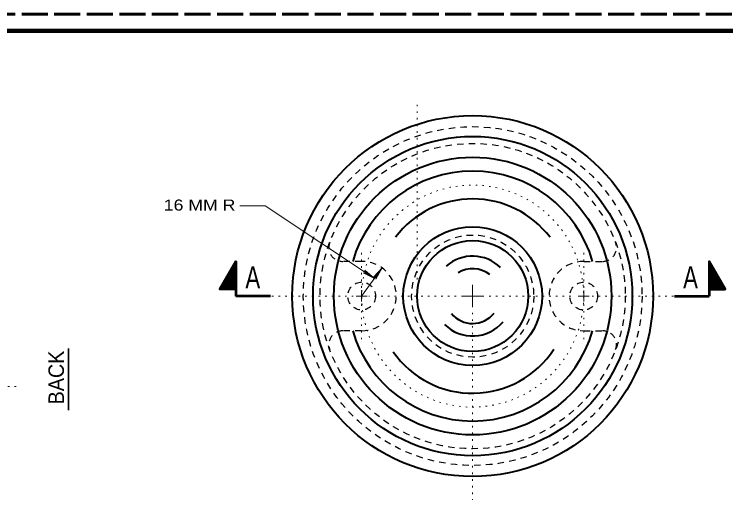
# Model space of a CAD drawing. Extents: x 312583 to 312853, y 144419 to 144586.
# Drawn here: x 312716.69 to 312765.82, y 144552.16 to 144586.22 of the extents above; entities that cross this region are included whole.
import ezdxf
from ezdxf.enums import TextEntityAlignment as Align

# ---------------------------------------------------------------- set-up
doc = ezdxf.new("R2010")
doc.units = 0
doc.header["$LTSCALE"] = 0.3
for name, pattern in [('DOTTED', [1.5, 0.3, -1.2]), ('LONG_DASHED', [7.5, 6, -1.5]), ('SHORT_DASHED', [2.7, 1.5, -1.2])]:
    doc.linetypes.add(name, pattern=pattern)
for name, color, linetype, lineweight in [('1', 7, 'Continuous', 40), ('2', 7, 'Continuous', 13), ('63', 7, 'LONG_DASHED', 60)]:
    doc.layers.add(name, color=color, linetype=linetype, lineweight=lineweight)

msp = doc.modelspace()

# ---------------------------------------------------------------- linework, layer by layer
at = {"layer": '1', "lineweight": 35}
for p, q in [((312731.9925, 144569.0873), (312731.9542, 144569.1103)), ((312731.9925, 144569.1179), (312731.9695, 144569.1256)), ((312731.9925, 144569.1486), (312731.9772, 144569.1486)), ((312764.6679, 144569.1486), (312764.6832, 144569.1486)), ((312764.6679, 144569.1179), (312764.6909, 144569.1256)), ((312764.6679, 144569.0873), (312764.7062, 144569.1103)), ((312731.9925, 144568.4509), (312731.6859, 144568.6273)), ((312731.9925, 144568.4816), (312731.6935, 144568.6503)), ((312731.9925, 144568.5123), (312731.7089, 144568.6733)), ((312731.9925, 144568.5353), (312731.7165, 144568.6886)), ((312731.9925, 144568.5659), (312731.7319, 144568.7193)), ((312731.9925, 144568.5889), (312731.7395, 144568.7346)), ((312731.9925, 144568.6196), (312731.7549, 144568.7576)), ((312731.9925, 144568.6503), (312731.7625, 144568.7806)), ((312731.9925, 144568.6733), (312731.7779, 144568.7959)), ((312731.9925, 144568.7039), (312731.7855, 144568.8189)), ((312731.9925, 144568.7269), (312731.8009, 144568.8419)), ((312731.9925, 144568.7576), (312731.8162, 144568.8573)), ((312731.9925, 144568.7883), (312731.8239, 144568.8803)), ((312731.9925, 144568.8189), (312731.8392, 144568.9033)), ((312731.9925, 144568.8419), (312731.8545, 144568.9186)), ((312731.9925, 144568.8726), (312731.8622, 144568.9416)), ((312731.9925, 144568.8956), (312731.8775, 144568.9646)), ((312731.9925, 144568.9186), (312731.8852, 144568.9876)), ((312731.9925, 144568.9493), (312731.9005, 144569.0029)), ((312731.9925, 144568.9799), (312731.9082, 144569.0259)), ((312731.9925, 144569.0106), (312731.9235, 144569.0489)), ((312731.9925, 144569.0336), (312731.9312, 144569.0643)), ((312731.9925, 144569.0643), (312731.9465, 144569.0873)), ((312764.6679, 144569.0643), (312764.7139, 144569.0873)), ((312764.6679, 144569.0336), (312764.7292, 144569.0643)), ((312764.6679, 144569.0106), (312764.7369, 144569.0489)), ((312764.6679, 144568.9799), (312764.7522, 144569.0259)), ((312764.6679, 144568.9493), (312764.7599, 144569.0029)), ((312764.6679, 144568.9186), (312764.7752, 144568.9876)), ((312764.6679, 144568.8956), (312764.7829, 144568.9646)), ((312764.6679, 144568.8726), (312764.7982, 144568.9416)), ((312764.6679, 144568.8419), (312764.8059, 144568.9186)), ((312764.6679, 144568.8189), (312764.8212, 144568.9033)), ((312764.6679, 144568.7883), (312764.8365, 144568.8803)), ((312764.6679, 144568.7576), (312764.8442, 144568.8573)), ((312764.6679, 144568.7269), (312764.8595, 144568.8419)), ((312764.6679, 144568.7039), (312764.8749, 144568.8189)), ((312764.6679, 144568.6733), (312764.8825, 144568.7959)), ((312764.6679, 144568.6503), (312764.8979, 144568.7806)), ((312764.6679, 144568.6196), (312764.9055, 144568.7576)), ((312764.6679, 144568.5889), (312764.9209, 144568.7346)), ((312764.6679, 144568.5659), (312764.9285, 144568.7193)), ((312764.6679, 144568.5353), (312764.9439, 144568.6886)), ((312764.6679, 144568.5123), (312764.9515, 144568.6733)), ((312764.6679, 144568.4816), (312764.9669, 144568.6503)), ((312764.6679, 144568.4509), (312764.9745, 144568.6273)), ((312731.9925, 144567.7916), (312731.3945, 144568.1289)), ((312731.9925, 144567.8223), (312731.4099, 144568.1519)), ((312731.9925, 144567.8453), (312731.4175, 144568.1749)), ((312731.9925, 144567.8759), (312731.4329, 144568.1903)), ((312731.9849, 144567.8989), (312731.4405, 144568.2209)), ((312731.9925, 144567.9296), (312731.4559, 144568.2363)), ((312731.9925, 144567.9526), (312731.4712, 144568.2593)), ((312731.9925, 144567.9833), (312731.4789, 144568.2823)), ((312731.9925, 144568.0139), (312731.4942, 144568.2976)), ((312731.9925, 144568.0369), (312731.5019, 144568.3206)), ((312731.9925, 144568.0676), (312731.5172, 144568.3436)), ((312731.9925, 144568.0983), (312731.5249, 144568.3589)), ((312731.9925, 144568.1213), (312731.5402, 144568.3819)), ((312731.9925, 144568.1519), (312731.5479, 144568.4049)), ((312731.9925, 144568.1826), (312731.5632, 144568.4203)), ((312731.9925, 144568.2056), (312731.5709, 144568.4433)), ((312731.9925, 144568.2286), (312731.5862, 144568.4663)), ((312731.9925, 144568.2593), (312731.5939, 144568.4893)), ((312731.9925, 144568.2899), (312731.6092, 144568.5046)), ((312731.9925, 144568.3206), (312731.6245, 144568.5276)), ((312731.9925, 144568.3436), (312731.6322, 144568.5506)), ((312731.9925, 144568.3743), (312731.6475, 144568.5659)), ((312731.9925, 144568.3973), (312731.6629, 144568.5889)), ((312731.9925, 144568.4279), (312731.6705, 144568.6119)), ((312764.6679, 144568.4279), (312764.9899, 144568.6119)), ((312764.6679, 144568.3973), (312764.9975, 144568.5889)), ((312764.6679, 144568.3743), (312765.0129, 144568.5659)), ((312764.6679, 144568.3436), (312765.0282, 144568.5506)), ((312764.6679, 144568.3206), (312765.0359, 144568.5276)), ((312764.6679, 144568.2899), (312765.0512, 144568.5046)), ((312764.6679, 144568.2593), (312765.0665, 144568.4893)), ((312764.6679, 144568.2286), (312765.0742, 144568.4663)), ((312764.6679, 144568.2056), (312765.0895, 144568.4433)), ((312764.6679, 144568.1826), (312765.0972, 144568.4203)), ((312764.6679, 144568.1519), (312765.1125, 144568.4049)), ((312764.6679, 144568.1213), (312765.1202, 144568.3819)), ((312764.6679, 144568.0983), (312765.1355, 144568.3589)), ((312764.6679, 144568.0676), (312765.1432, 144568.3436)), ((312764.6679, 144568.0369), (312765.1585, 144568.3206)), ((312764.6679, 144568.0139), (312765.1662, 144568.2976)), ((312764.6679, 144567.9833), (312765.1815, 144568.2823)), ((312764.6679, 144567.9526), (312765.1892, 144568.2593)), ((312764.6679, 144567.9296), (312765.2045, 144568.2363)), ((312764.6679, 144567.8759), (312765.2275, 144568.1903)), ((312764.6679, 144567.8453), (312765.2429, 144568.1749)), ((312764.6679, 144567.8223), (312765.2505, 144568.1519)), ((312764.6679, 144567.7916), (312765.2659, 144568.1289)), ((312764.6755, 144567.8989), (312765.2199, 144568.2209)), ((312731.8239, 144567.2473), (312731.1262, 144567.6536)), ((312731.8775, 144567.2473), (312731.1339, 144567.6766)), ((312731.9159, 144567.2473), (312731.1492, 144567.6919)), ((312731.9695, 144567.2473), (312731.1569, 144567.7226)), ((312731.9925, 144567.2626), (312731.1722, 144567.7379)), ((312731.9925, 144567.2933), (312731.1799, 144567.7609)), ((312731.9925, 144567.3239), (312731.1952, 144567.7839)), ((312731.9925, 144567.3469), (312731.2029, 144567.7993)), ((312731.9925, 144567.3776), (312731.2182, 144567.8223)), ((312731.9849, 144567.4006), (312731.2259, 144567.8453)), ((312731.9849, 144567.4313), (312731.2412, 144567.8606)), ((312731.9925, 144567.4543), (312731.2489, 144567.8836)), ((312731.9925, 144567.4849), (312731.2642, 144567.9066)), ((312731.9925, 144567.5156), (312731.2795, 144567.9219)), ((312731.9925, 144567.5386), (312731.2872, 144567.9449)), ((312731.9925, 144567.5693), (312731.3025, 144567.9679)), ((312731.9925, 144567.5999), (312731.3179, 144567.9909)), ((312731.9925, 144567.6229), (312731.3255, 144568.0063)), ((312731.9849, 144567.6536), (312731.3409, 144568.0293)), ((312731.9925, 144567.6843), (312731.3485, 144568.0523)), ((312731.9925, 144567.7073), (312731.3639, 144568.0676)), ((312731.9925, 144567.7303), (312731.3715, 144568.0906)), ((312731.9925, 144567.7609), (312731.3869, 144568.1136)), ((312764.6679, 144567.7609), (312765.2735, 144568.1136)), ((312764.6679, 144567.7303), (312765.2889, 144568.0906)), ((312764.6679, 144567.7073), (312765.2965, 144568.0676)), ((312764.6679, 144567.6843), (312765.3119, 144568.0523)), ((312764.6679, 144567.6229), (312765.3349, 144568.0063)), ((312764.6679, 144567.5999), (312765.3425, 144567.9909)), ((312764.6679, 144567.5693), (312765.3579, 144567.9679)), ((312764.6679, 144567.5386), (312765.3732, 144567.9449)), ((312764.6679, 144567.5156), (312765.3809, 144567.9219)), ((312764.6679, 144567.4849), (312765.3962, 144567.9066)), ((312764.6679, 144567.4543), (312765.4115, 144567.8836)), ((312764.6679, 144567.3776), (312765.4422, 144567.8223)), ((312764.6679, 144567.3469), (312765.4575, 144567.7993)), ((312764.6679, 144567.3239), (312765.4652, 144567.7839)), ((312764.6679, 144567.2933), (312765.4805, 144567.7609)), ((312764.6679, 144567.2626), (312765.4882, 144567.7379)), ((312764.6755, 144567.6536), (312765.3195, 144568.0293)), ((312764.6755, 144567.4313), (312765.4192, 144567.8606)), ((312764.6755, 144567.4006), (312765.4345, 144567.8453)), ((312764.6909, 144567.2473), (312765.5035, 144567.7226)), ((312764.7445, 144567.2473), (312765.5112, 144567.6919)), ((312764.7829, 144567.2473), (312765.5265, 144567.6766)), ((312764.8365, 144567.2473), (312765.5342, 144567.6536)), ((312730.9115, 144567.2473), (312730.8962, 144567.2626)), ((312730.9575, 144567.2473), (312730.9039, 144567.2856)), ((312731.0112, 144567.2473), (312730.9192, 144567.3009)), ((312731.0572, 144567.2473), (312730.9345, 144567.3239)), ((312731.1109, 144567.2473), (312730.9422, 144567.3469)), ((312731.1492, 144567.2473), (312730.9575, 144567.3623)), ((312731.2029, 144567.2473), (312730.9652, 144567.3853)), ((312731.2489, 144567.2473), (312730.9805, 144567.4083)), ((312731.2949, 144567.2473), (312730.9882, 144567.4236)), ((312731.3409, 144567.2473), (312731.0035, 144567.4543)), ((312731.3945, 144567.2473), (312731.0112, 144567.4696)), ((312731.4405, 144567.2473), (312731.0265, 144567.4926)), ((312731.4865, 144567.2473), (312731.0342, 144567.5156)), ((312731.5402, 144567.2473), (312731.0495, 144567.5309)), ((312731.5862, 144567.2473), (312731.0572, 144567.5539)), ((312731.6322, 144567.2473), (312731.0725, 144567.5693)), ((312731.6859, 144567.2473), (312731.0879, 144567.5923)), ((312731.7319, 144567.2473), (312731.0955, 144567.6153)), ((312731.7779, 144567.2473), (312731.1109, 144567.6306)), ((312764.8825, 144567.2473), (312765.5495, 144567.6306)), ((312764.9285, 144567.2473), (312765.5649, 144567.6153)), ((312764.9745, 144567.2473), (312765.5725, 144567.5923)), ((312765.0282, 144567.2473), (312765.5879, 144567.5693)), ((312765.0742, 144567.2473), (312765.6032, 144567.5539)), ((312765.1202, 144567.2473), (312765.6109, 144567.5309)), ((312765.1739, 144567.2473), (312765.6262, 144567.5156)), ((312765.2199, 144567.2473), (312765.6339, 144567.4926)), ((312765.2659, 144567.2473), (312765.6492, 144567.4696)), ((312765.3195, 144567.2473), (312765.6569, 144567.4543)), ((312765.3655, 144567.2473), (312765.6722, 144567.4236)), ((312765.4115, 144567.2473), (312765.6799, 144567.4083)), ((312765.4575, 144567.2473), (312765.6952, 144567.3853)), ((312765.5112, 144567.2473), (312765.7029, 144567.3623)), ((312765.5495, 144567.2473), (312765.7182, 144567.3469)), ((312765.6032, 144567.2473), (312765.7259, 144567.3239)), ((312765.6492, 144567.2473), (312765.7412, 144567.3009)), ((312765.7029, 144567.2473), (312765.7565, 144567.2856)), ((312765.7489, 144567.2473), (312765.7642, 144567.2626))]:
    msp.add_line(p, q, dxfattribs=at)
at = {"layer": '1', "linetype": 'SHORT_DASHED', "lineweight": 25}
for p, q in [((312740.6789, 144569.1639), (312739.3679, 144569.1639)), ((312756.0122, 144569.1639), (312757.3232, 144569.1639)), ((312740.6789, 144564.3723), (312739.3679, 144564.3723)), ((312756.0122, 144564.3723), (312757.3232, 144564.3723))]:
    msp.add_line(p, q, dxfattribs=at)
at = {"layer": '1', "lineweight": 53}
for p, q in [((312731.9925, 144567.2473), (312731.9925, 144566.7719)), ((312764.6679, 144567.2473), (312764.6679, 144566.7719)), ((312734.3845, 144566.7719), (312731.9925, 144566.7719)), ((312762.2759, 144566.7719), (312764.6679, 144566.7719))]:
    msp.add_line(p, q, dxfattribs=at)
at = {"layer": '1', "lineweight": 158}
msp.add_lwpolyline([(312616.5, 144423.1446), (312616.5, 144585.0846), (312849, 144585.0846)], dxfattribs=at)
at = {"layer": '1', "lineweight": 53}
for points in [[(312731.9925, 144567.2473), (312730.8809, 144567.2473), (312731.9925, 144569.1639)], [(312764.6679, 144567.2473), (312765.7795, 144567.2473), (312764.6679, 144569.1639)]]:
    msp.add_lwpolyline(points, close=True, dxfattribs=at)
at = {"layer": '1'}
for radius in [12.4583, 11.0208, 9.5833, 4.7917, 3.8333]:
    msp.add_circle((312748.3455, 144566.7681), radius, dxfattribs=at)
at = {"layer": '1', "linetype": 'SHORT_DASHED', "lineweight": 25}
for centre, radius in [((312748.3455, 144566.7681), 11.6955), ((312748.3455, 144566.7681), 10.5417), ((312748.3455, 144566.7681), 4.2167), ((312740.6789, 144566.7681), 0.9583), ((312756.0122, 144566.7681), 0.9583)]:
    msp.add_circle(centre, radius, dxfattribs=at)
at = {"layer": '1', "linetype": 'DOTTED', "lineweight": 13}
msp.add_circle((312748.3455, 144566.7681), 7.6667, dxfattribs=at)
at = {"layer": '1'}
for radius, start, end in [(8.625, 16.12762, 163.86918), (6.7083, 37.2286, 142.63286), (2.7568, 45.50703, 131.50106), (1.8925, 51.63616, 121.91926), (1.8925, 219.65694, 321.18094), (2.7568, 225.38233, 319.79641), (8.625, 196.12762, 343.86918), (6.7083, 215.00759, 326.84244)]:
    msp.add_arc((312748.3455, 144566.7681), radius, start, end, dxfattribs=at)
at = {"layer": '1', "linetype": 'SHORT_DASHED', "lineweight": 25}
for centre, radius, start, end in [((312739.3683, 144570.1223), 0.9583, 159.51269, 270), ((312757.3227, 144570.1223), 0.9583, 270, 20.48731), ((312740.6789, 144566.7681), 2.3958, 270, 90), ((312756.0122, 144566.7681), 2.3958, 90, 270), ((312739.3683, 144563.4139), 0.9583, 90, 200.48731), ((312757.3227, 144563.4139), 0.9583, 339.51269, 90)]:
    msp.add_arc(centre, radius, start, end, dxfattribs=at)
at = {"layer": '2', "linetype": 'DOTTED'}
for p, q in [((312744.5186, 144567.9219), (312744.5186, 144580.2346)), ((312740.6789, 144567.3469), (312740.6789, 144570.0839)), ((312756.0122, 144567.3469), (312756.0122, 144569.9919)), ((312740.1039, 144566.7719), (312734.3845, 144566.7719)), ((312747.1955, 144566.7719), (312741.1849, 144566.7719)), ((312749.4955, 144566.7719), (312755.3759, 144566.7719)), ((312756.5872, 144566.7719), (312762.2759, 144566.7719)), ((312740.6789, 144566.1969), (312740.6789, 144563.5903)), ((312756.0122, 144566.1969), (312756.0122, 144563.5596)), ((312748.3455, 144565.6219), (312748.3455, 144552.6959)), ((312702.4508, 144560.5276), (312716.9715, 144560.5276))]:
    msp.add_line(p, q, dxfattribs=at)
at = {"layer": '2'}
for p, q in [((312740.6789, 144566.7719), (312742.0895, 144568.7116)), ((312742.0895, 144568.7116), (312741.4915, 144568.0676)), ((312742.0895, 144568.7116), (312741.6679, 144567.9449)), ((312740.7862, 144568.3819), (312741.0775, 144568.3129)), ((312741.5682, 144567.9909), (312740.7862, 144568.3819)), ((312740.9012, 144568.5583), (312741.0775, 144568.3129)), ((312741.5682, 144567.9909), (312740.9012, 144568.5583)), ((312741.4915, 144568.0676), (312741.7445, 144568.2286)), ((312741.6679, 144567.9449), (312741.7445, 144568.2286)), ((312740.6789, 144566.7719), (312740.6789, 144567.1553)), ((312748.3455, 144566.7719), (312748.3455, 144567.5386)), ((312756.0122, 144566.7719), (312756.0122, 144567.1553)), ((312740.6789, 144566.7719), (312740.2955, 144566.7719)), ((312740.6789, 144566.7719), (312741.0622, 144566.7719)), ((312740.6789, 144566.7719), (312740.6789, 144566.3886)), ((312748.3455, 144566.7719), (312747.5789, 144566.7719)), ((312748.3455, 144566.7719), (312749.1122, 144566.7719)), ((312748.3455, 144566.7719), (312748.3455, 144566.0053)), ((312756.0122, 144566.7719), (312755.6289, 144566.7719)), ((312756.0122, 144566.7719), (312756.3955, 144566.7719)), ((312756.0122, 144566.7719), (312756.0122, 144566.3886))]:
    msp.add_line(p, q, dxfattribs=at)
at = {"layer": '2', "lineweight": 35}
msp.add_line((312720.4368, 144558.8859), (312720.4368, 144563.1413), dxfattribs=at)
at = {"layer": '2'}
msp.add_lwpolyline([(312741.5682, 144567.9909), (312734.0089, 144573.0049), (312732.2609, 144573.0049)], dxfattribs=at)
at = {"layer": '63'}
msp.add_line((312851.75, 144586.2246), (312583.526, 144586.2246), dxfattribs=at)

# ---------------------------------------------------------------- texts
at = {"layer": '1', "width": 0.75}
for p in [(312733.1617, 144567.2933), (312763.3914, 144567.2933)]:
    msp.add_text('A', height=1.533, dxfattribs=at).set_placement(p, align=Align.CENTER)
at = {"layer": '2', "width": 1.2}
msp.add_text('16 MM R', height=0.76, dxfattribs=at).set_placement((312727.0141, 144572.6724))
at = {"layer": '2', "width": 0.95}
msp.add_text('BACK', height=1.07, rotation=90, dxfattribs=at).set_placement((312720.1197, 144561.1472), align=Align.CENTER)

doc.saveas('drawing.dxf')
